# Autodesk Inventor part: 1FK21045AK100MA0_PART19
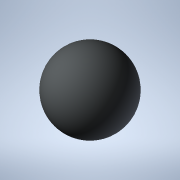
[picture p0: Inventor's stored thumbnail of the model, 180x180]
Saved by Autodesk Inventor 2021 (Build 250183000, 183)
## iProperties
Created: 2025-04
Part Number: 1FK21045AK100MA0_PART19
Material: Generic
Catalog Web Link: www.3dfindit.com
Description: -Servo synchronous motor
Document SubType Name: Modeling
Designer: psAdmin
Mass: 0.137258 g
Surface Area: 1.2868 cm^2
Volume: 0.137258 cm^3
Density: 1 g/cm^3
Appearance: PSOLRGB-212-217-219
Category: PARTsolutions
Title: 1FK21045AK100MA0_PART19
Author: Cadenas PARTsolutions
Comments: Servo synchronous motor
Sending System: PARTsolutions
Preprocessor: ST-DEVELOPER v19.3
PSOL_IDENT_0: {$CADENAS_DATA/23d-libs/siemens_ag/_cat_/e0/5f/1fk21045ak100ma0.prj},216 {VTYP=3D},{NB=1FK21045AK100
PSOL_IDENT_1: MA0_PART19},{LINA=1FK21045AK100MA0_PART19},{NN=1FK21045AK100MA0_PART19},{NOPRJ=TRUE},{DATE=19.08.202
PSOL_IDENT_2: 5 14:01:03},{GEOMDATE=30.07.2025 02:01:57},{VERSION=},{LINEID=10},{WBVAR=},{WBNUMERIC=}  {NB=1FK2104
PSOL_IDENT_3: 5AK100MA0_PART19},{LINA=1FK21045AK100MA0_PART19},{KT=DUMMY},{PREVIEW=../../../_pool_/0f/2c/p_d211_xx
PSOL_IDENT_4: _00438j.png},{DESCSHORT=SIMOTICS S-1FK2 HD, SINAMICS S210 3AC 400V-480V, 1.7 Nm, 6000 rpm},{DESCLONG=
PSOL_IDENT_5: SIMOTICS S-1FK2 HD servo motor M0=2.4 Nm; PN = 1.07 kW at nN=6000 rpm (380-480 V); PN = 0.75 kW at n
PSOL_IDENT_6: N=3000 rpm (200-240 V); with holding brake; degree of protection IP64; cylindrical shaft D19x40mm; a
PSOL_IDENT_7: bsolute encoder 22-bit + 12-bit multiturn (encoder AM22DQC); with OCC interface; plug size M17, rota
PSOL_IDENT_8: table; SIMOTICS S-1FK2 servomotorfor a wide range of uses in industrial environments. SIMOTICS S‑1FK
PSOL_IDENT_9: 2 servomotors are compact synchronous motors with a high dynamic performance that set themselves apa
PSOL_IDENT_10: rt as a result of their high power density, degree of protection and overload capability. The motors
PSOL_IDENT_11: are available in two variants: as High Dynamic variant (highest dynamic performance as a result of
PSOL_IDENT_12: the low intrinsic moment of inertia for applications demanding a high dynamic performance with low m
PSOL_IDENT_13: oved masses) - and as Compact variant (precise and stable closed-loop control for medium up to large
PSOL_IDENT_14: moved masses as a result of a medium intrinsic moment of inertia). SIMOTICSS‑1FK2 servomotors fully
PSOL_IDENT_15: exploit their strengths in a system with the SINAMICSS210 frequency converter and simple connection
PSOL_IDENT_16: using the one cable connection (OCC). Advantages include the short control and positioning times, f
PSOL_IDENT_17: ast and precise correction of disturbing quantities as well as stable control with a high dynamic pe
PSOL_IDENT_18: rformance. The servo motors can be configured to address a wide range of requirements. For example w
PSOL_IDENT_19: ith and without holding brake, IP64 or IP65 degree of protection, singleturn or multiturn absolute e
PSOL_IDENT_20: ncoders - to name just a few. Further, the servomotors are available in different shaft heights exte
PSOL_IDENT_21: nding from 20 to 100. A shaft sealing ring is available to achieve an IP65 degree of protection and
PSOL_IDENT_22: for subsequent mounting at the motor or as spare part. SIMOTICS - the optimum motor for each and eve
PSOL_IDENT_23: ry motion control application.},{INTNO=804766807114},{SUPPLIERALTNO=1FK2104-5AK10-0MA0},{MANUID=1FK2
PSOL_IDENT_24: 1045AK100MA0},{MANUNAME=Siemens},{MANUTYPEDESC=Synchronous motor 1FK2-HD 2,39 Nm},{AAU732=SIMOTICS},
PSOL_IDENT_25: {AAO057=S-1FK2},{AAU734=SIMOTICS S-1FK2 HD servo motor M0=2.4 Nm; PN = 1.07 kW at nN=6000 rpm (380-4
PSOL_IDENT_26: 80 V); PN = 0.75 kW at nN=3000 rpm (200-240 V); with holding brake; degree of protection IP64; cylin
PSOL_IDENT_27: drical shaft D19x40mm; absolute encoder 22-bit + 12-bit multiturn (encoder AM22DQC); with OCC interf
PSOL_IDENT_28: ace; plug size M17, rotatable;},{AAW338=Synchronous motor 1FK2-HD 2,39 Nm},{AAO742=SIMOTICS},{AAO663=
PSOL_IDENT_29: 4042948691236},{NOCUPEROU=1},{PRICEQUANTITY=1},{QUANTITYMIN=1},{QUANTITYINT=1},{CTN=85015100},{COO=D
PSOL_IDENT_30: E},{AAO676=1FK2104-5AK10-0MA0},{AAO677=Siemens AG},{ORDERUNIT=C62},{CONTENTUNIT=C62}
NB: 1FK21045AK100MA0_PART19
NT: Servo synchronous motor
NBSYN: $MANUID._PART19
LINA: 1FK21045AK100MA0_PART19
CATALOG: SIEMENS
PREVIEW: ../../../_pool_/0f/2c/p_d211_xx_00438j.png
DESCSHORT: SIMOTICS S-1FK2 HD, SINAMICS S210 3AC 400V-480V, 1.7 Nm, 6000 rpm
DESCLONG: SIMOTICS S-1FK2 HD servo motor M0=2.4 Nm; PN = 1.07 kW at nN=6000 rpm (380-480 V); PN = 0.75 kW at nN=3000 rpm (200-240 V); with holding brake; degree of protec
INTNO: 804766807114
SUPPLIERALTNO: 1FK2104-5AK10-0MA0
MANUID: 1FK21045AK100MA0
MANUNAME: Siemens
MANUTYPEDESC: Synchronous motor 1FK2-HD 2,39 Nm
AAU732: SIMOTICS
AAO057: S-1FK2
AAU734: SIMOTICS S-1FK2 HD servo motor M0=2.4 Nm; PN = 1.07 kW at nN=6000 rpm (380-480 V); PN = 0.75 kW at nN=3000 rpm (200-240 V); with holding brake; degree of protec
AAW338: Synchronous motor 1FK2-HD 2,39 Nm
AAO742: SIMOTICS
AAO663: 4042948691236.0
NOCUPEROU: 1
PRICEQUANTITY: 1
QUANTITYMIN: 1
QUANTITYINT: 1
CTN: 85015100
COO: DE
ARTICLENO: 1FK21045AK100MA0_PART19
BOMINFO: 1FK21045AK100MA0_PART19
CREATOR: CADENAS GmbH
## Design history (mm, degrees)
feature "2025_04_17_15_45_15_0090"
body "Solid1"
